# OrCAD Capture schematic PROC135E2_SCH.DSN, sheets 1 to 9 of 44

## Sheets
1 01. TABLE OF CONTENTS: title: TABLE OF CONTENTS; rev: E2
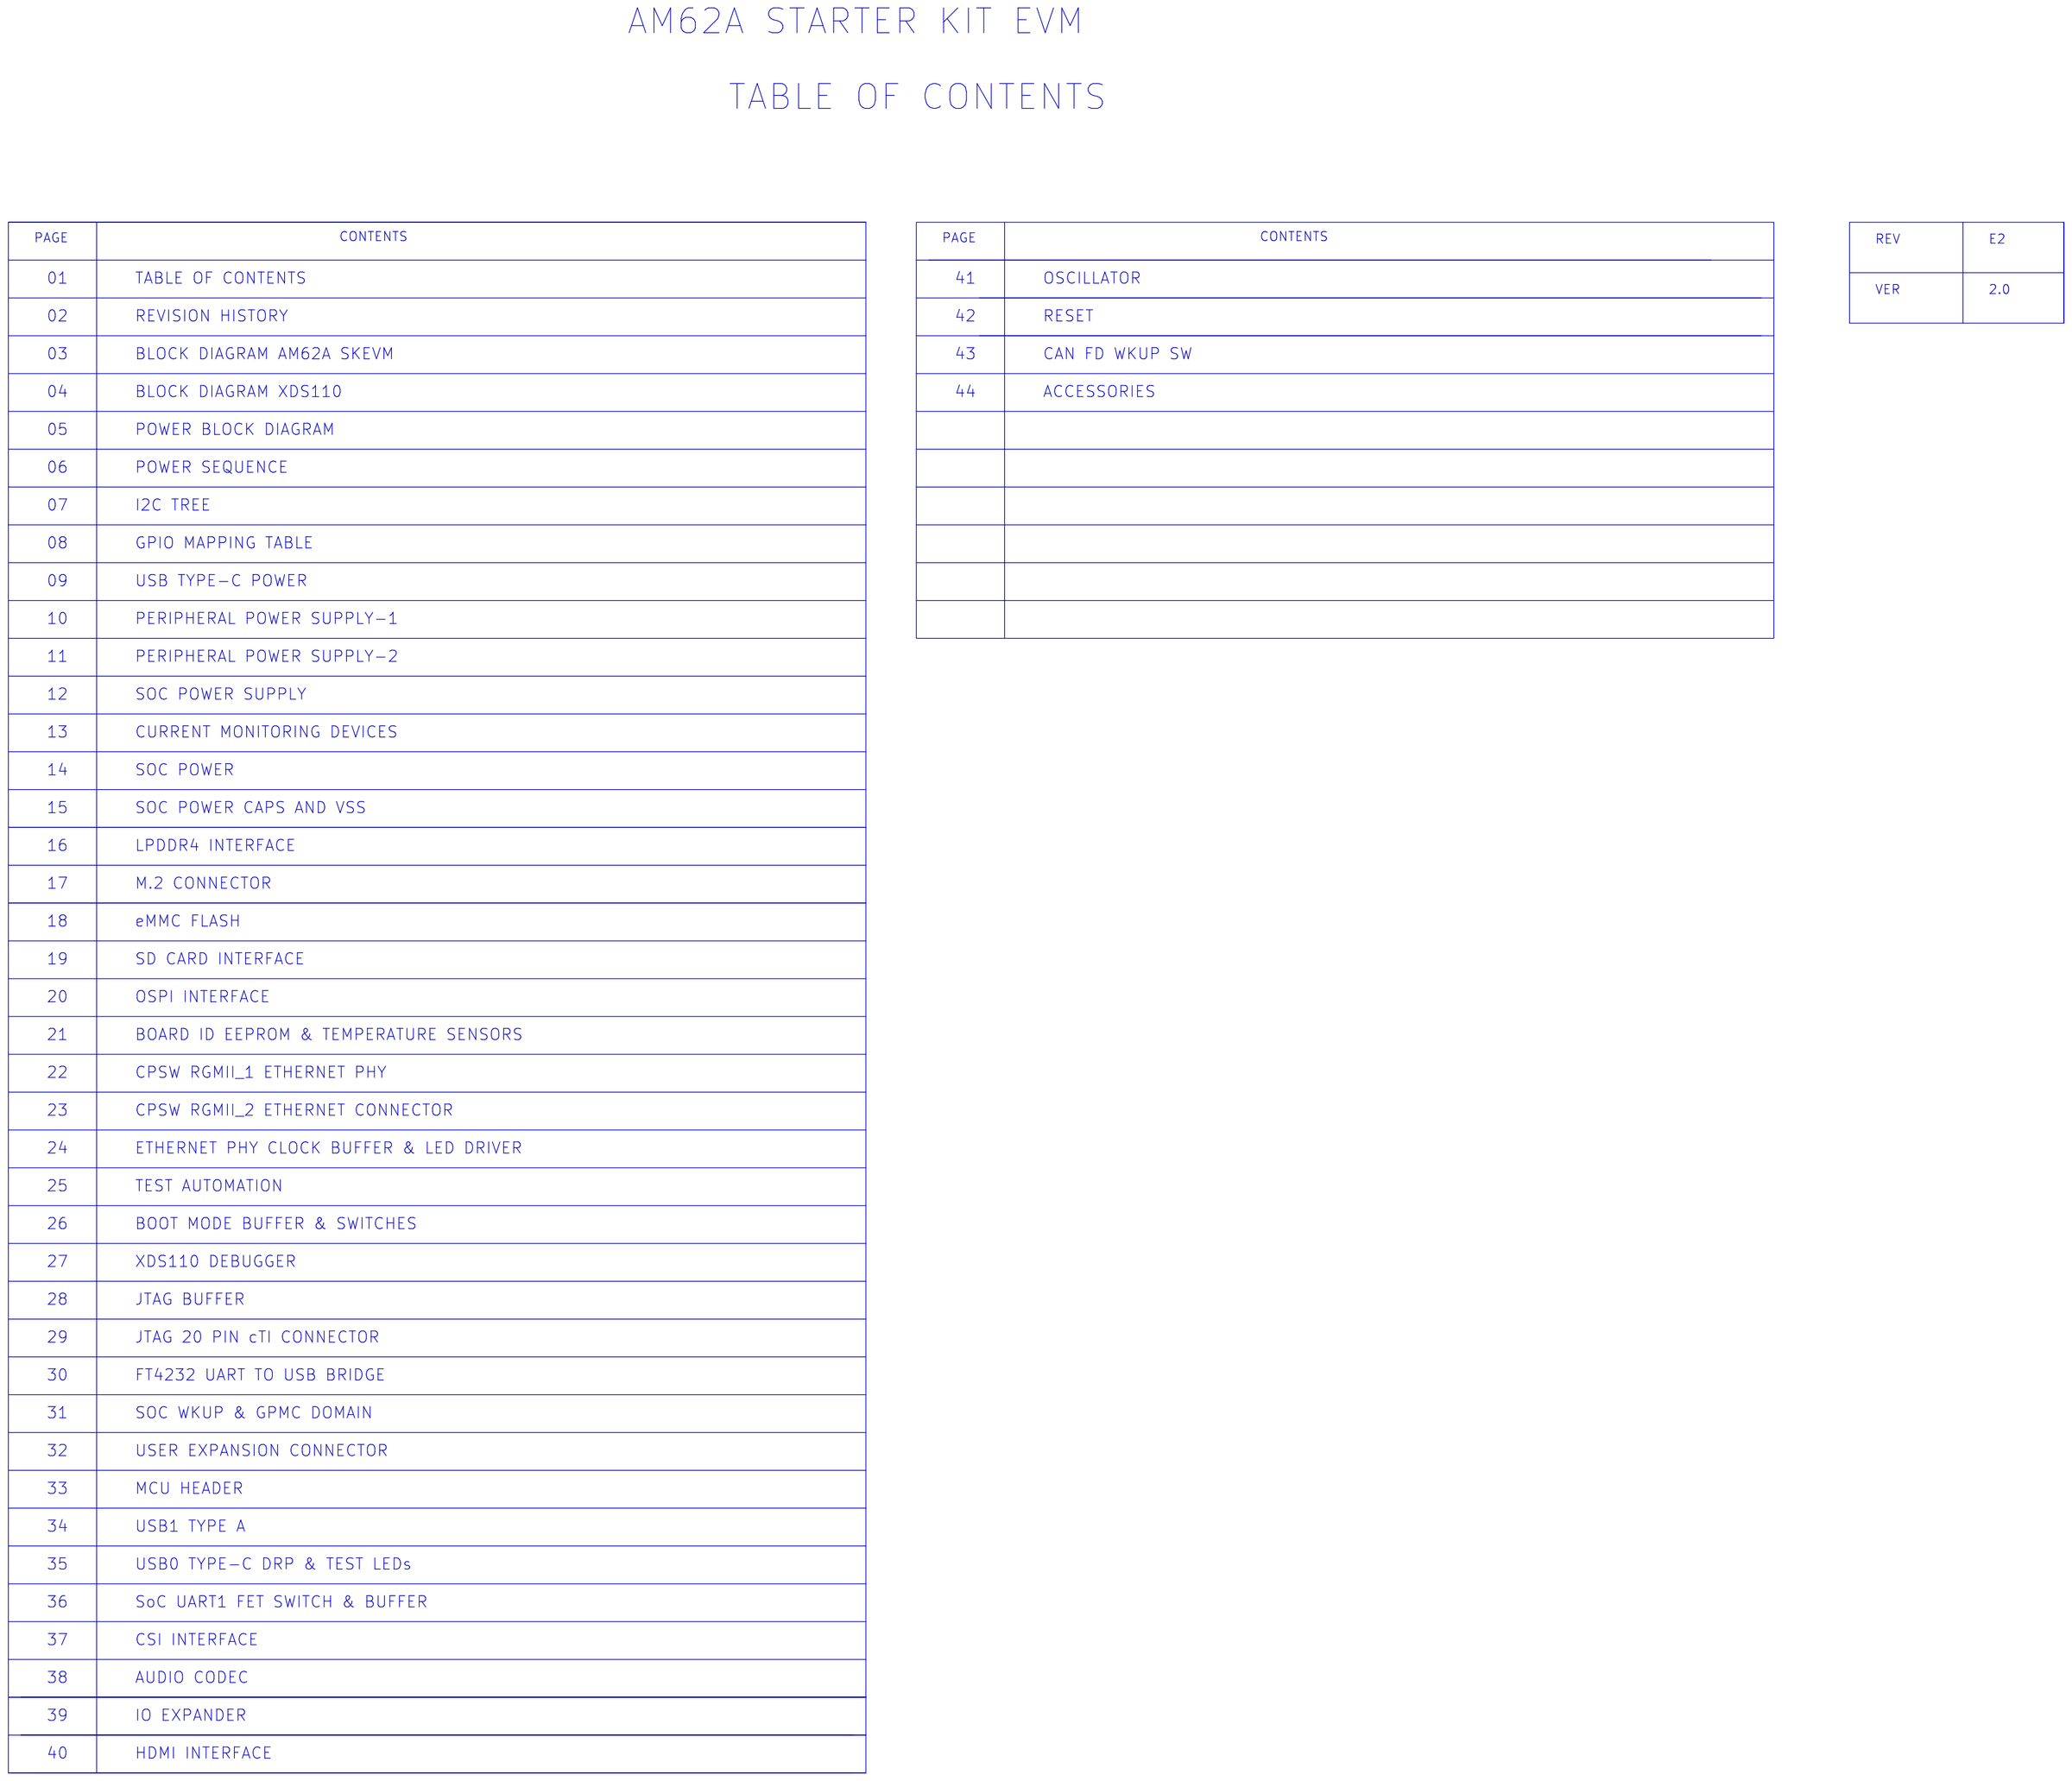
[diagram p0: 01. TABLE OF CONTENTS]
2 02. REVISION HISTORY: title: REVISION HISTORY
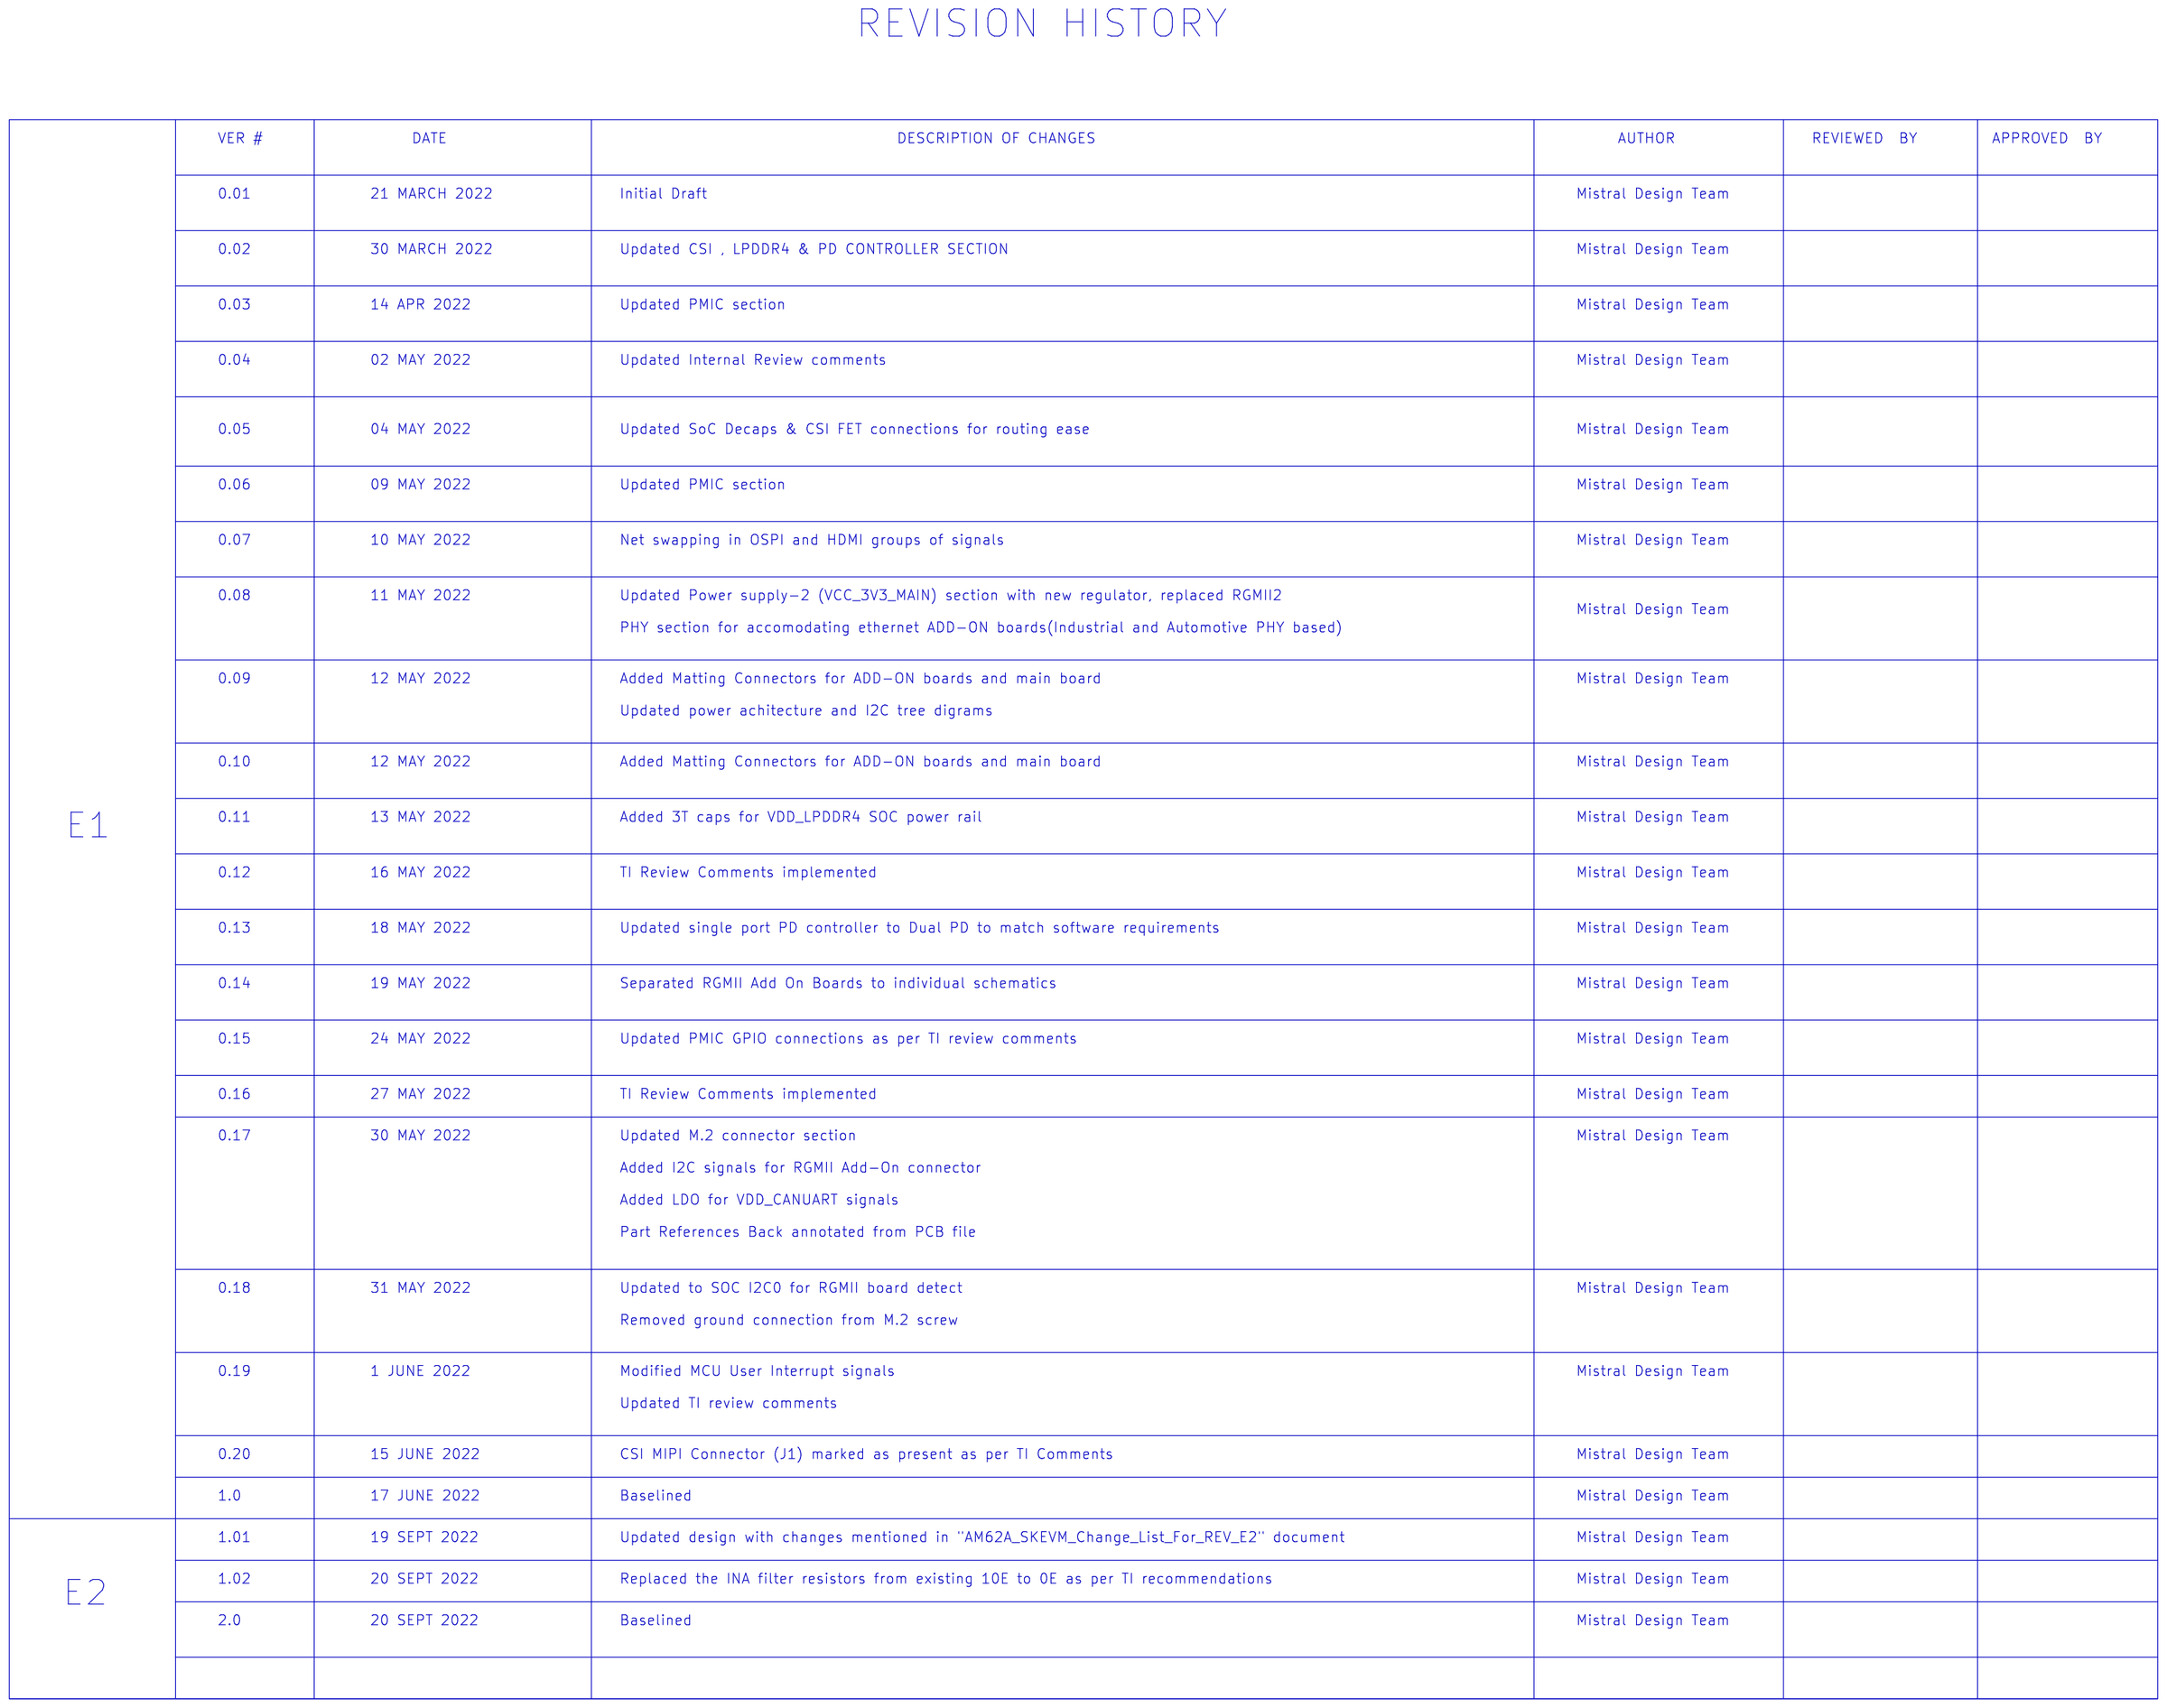
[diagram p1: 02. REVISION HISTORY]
3 03. BLOCK DGM AM62A-SKEVM: title: BLOCK DIAGRAM AM62A_ SKEVM
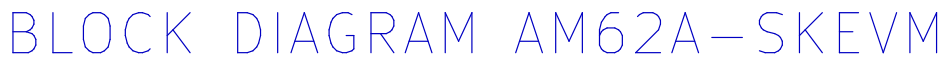
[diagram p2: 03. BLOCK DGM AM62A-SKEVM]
4 04. BLOCK DIAGRAM_XDS110: title: BLOCK DIAGRAM_XDS110
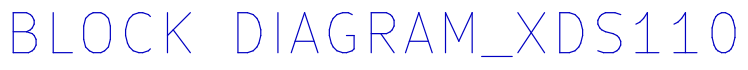
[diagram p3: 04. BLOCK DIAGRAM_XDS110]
5 05. POWER BLOCK DGM: title: POWER BLOCK DGM
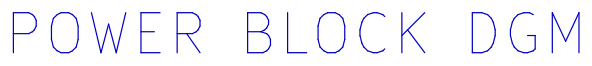
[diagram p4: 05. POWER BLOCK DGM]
6 06. POWER SEQUENCE: title: POWER SEQUENCE
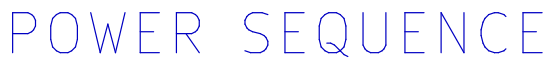
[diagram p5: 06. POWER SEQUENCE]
7 07. I2C TREE: title: I2C TREE
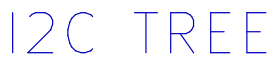
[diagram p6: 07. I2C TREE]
8 08. GPIO MAPPING TABLE: title: GPIO MAPPING TABLE
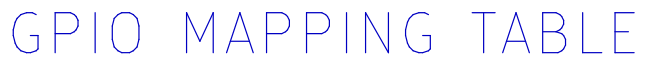
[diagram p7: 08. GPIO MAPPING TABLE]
9 09. USB TYPE-C POWER: size C; title: USB TYPE-C
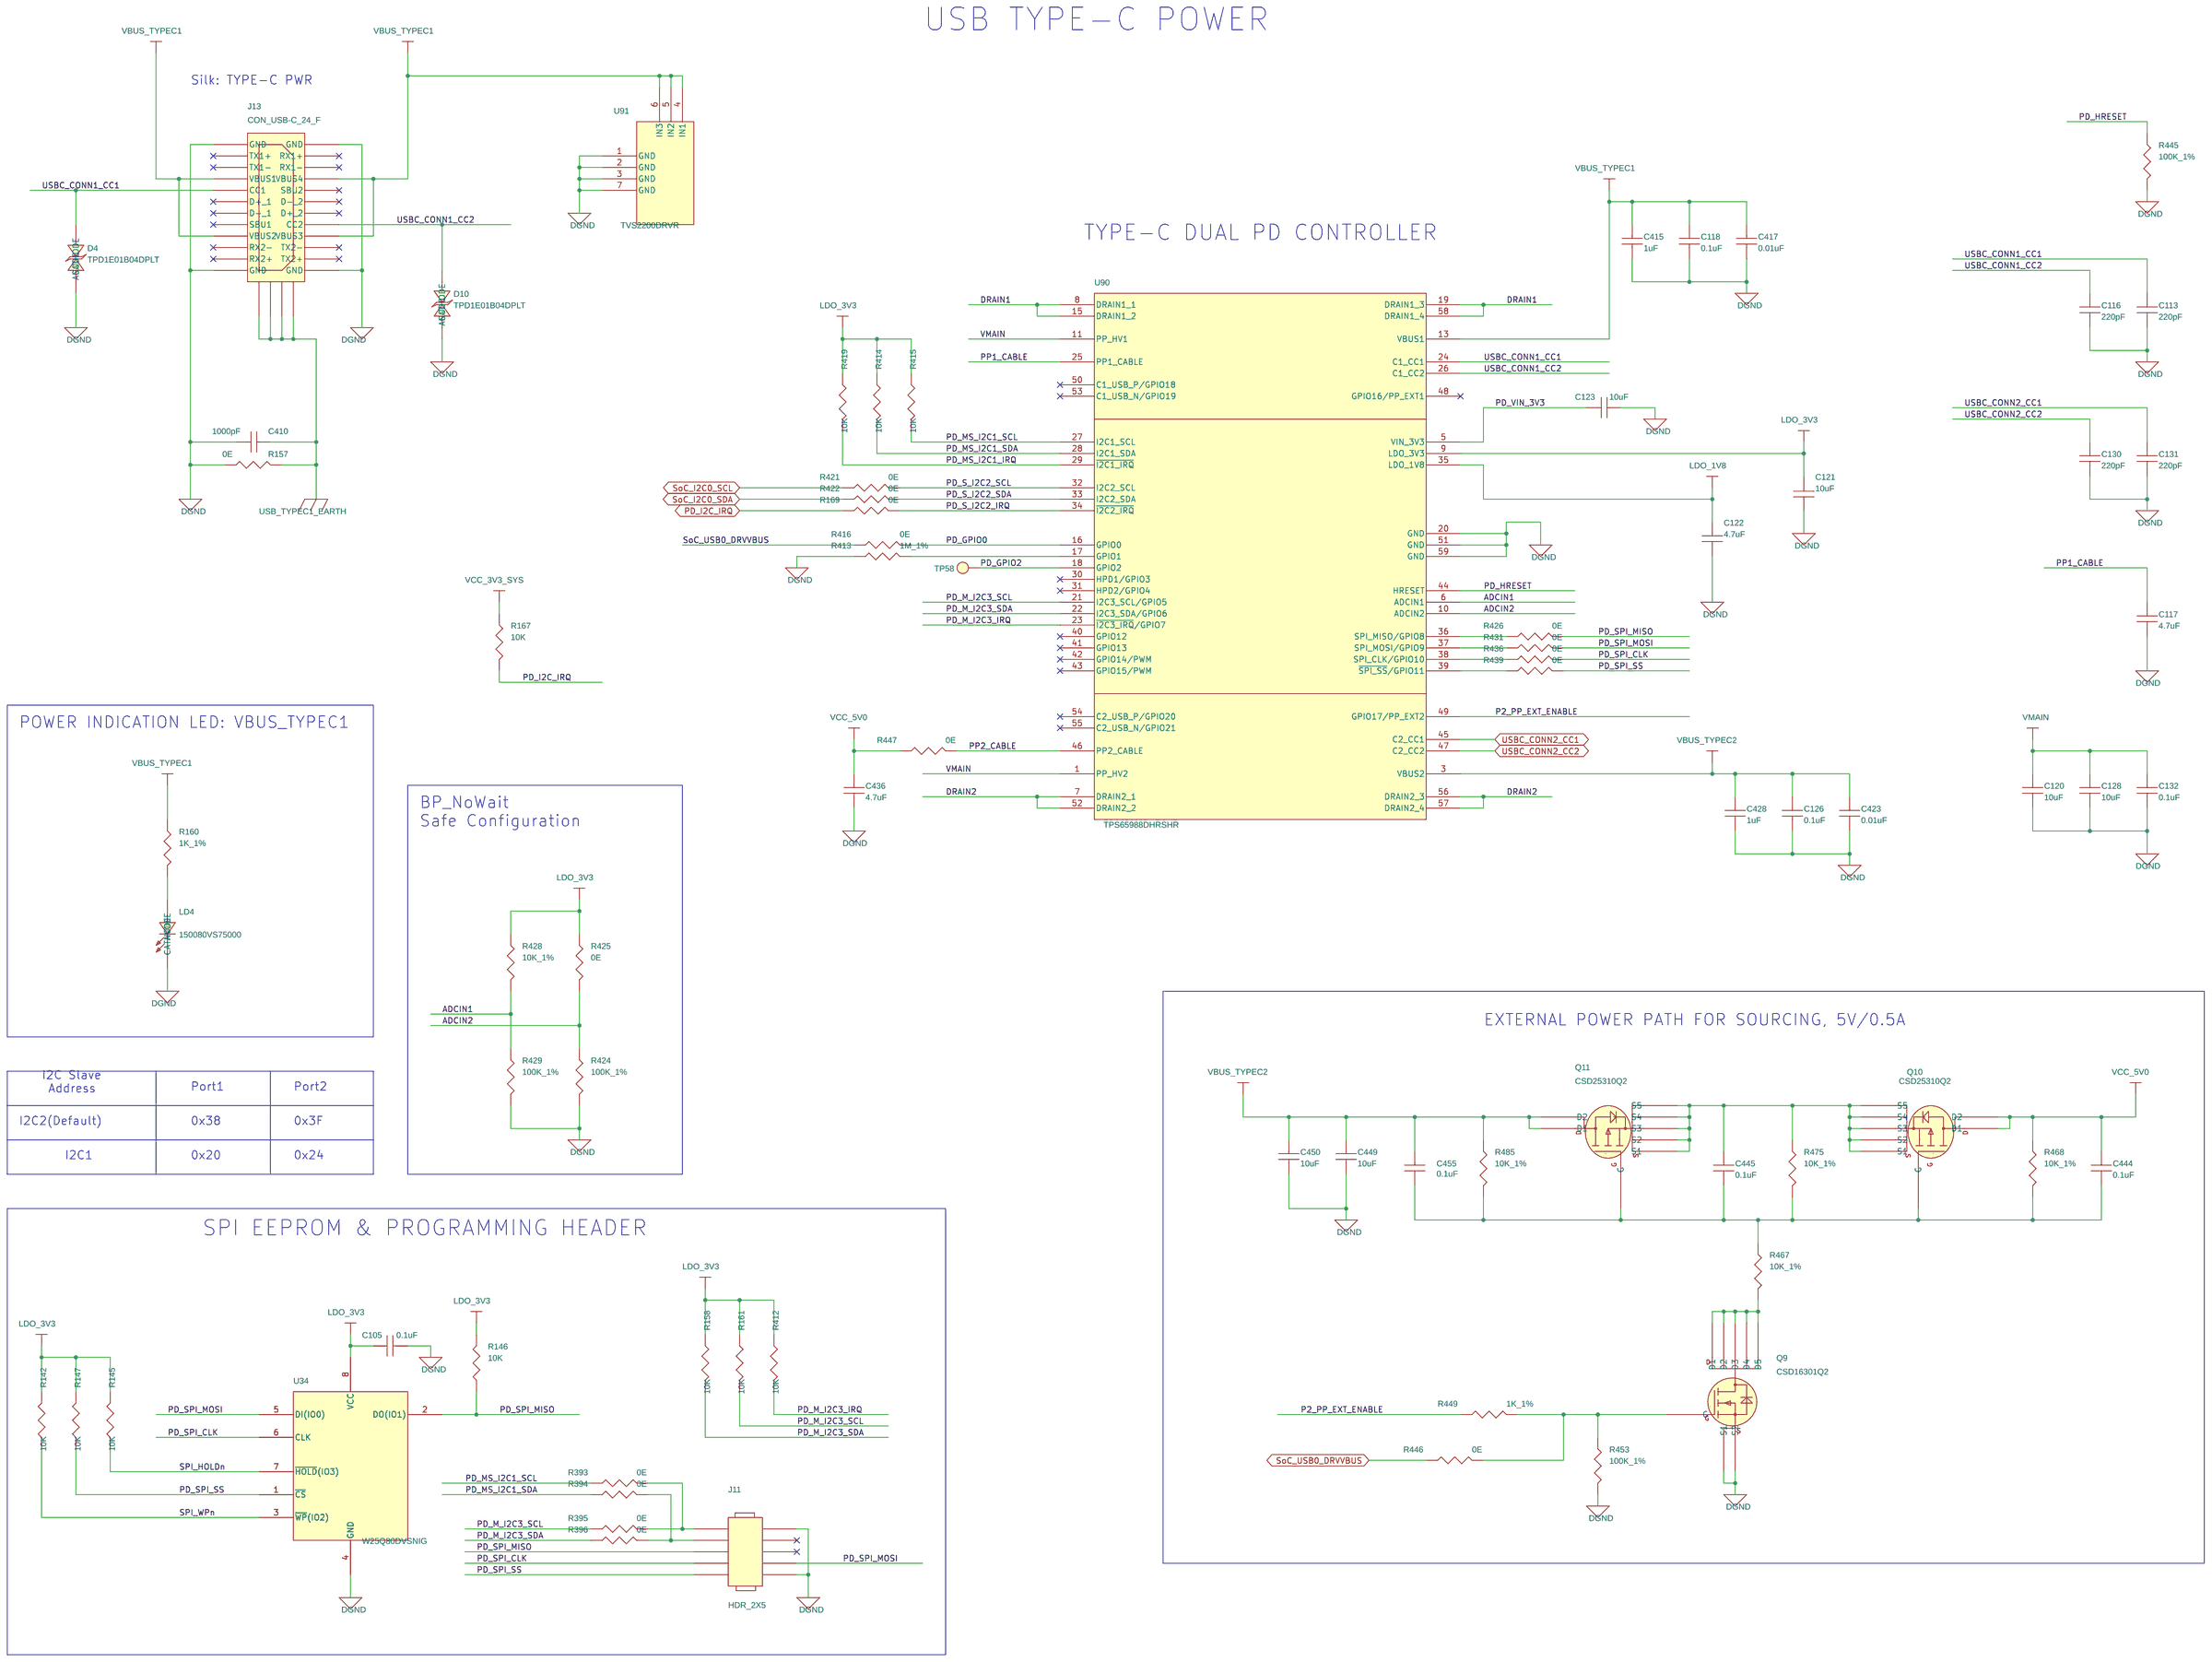
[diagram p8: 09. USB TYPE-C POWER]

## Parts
C105  0.1uF  [CAP0201_0-5]
C113  220pF  [CAP0402_0-75]
C116  220pF  [CAP0402_0-75]
C117  4.7uF  [CAP0402_0-75]
C118  0.1uF  [CAP0402_0-75]
C120  10uF  [CAP0603_1]
C121  10uF  [CAP0402_0-75]
C122  4.7uF  [CAP0402_0-75]
C123  10uF  [CAP0402_0-75]
C126  0.1uF  [CAP0402_0-75]
C128  10uF  [CAP0603_1]
C130  220pF  [CAP0402_0-75]
C131  220pF  [CAP0402_0-75]
C132  0.1uF  [CAP0402_0-75]
C410  1000pF  [CAP1206_1-75]
C415  1uF  [CAP0805_1-5]
C417  0.01uF  [CAP0201_0-5]
C423  0.01uF  [CAP0201_0-5]
C428  1uF  [CAP0805_1-5]
C436  4.7uF  [CAP0402_0-75]
C444  0.1uF  [CAP0201_0-5]
C445  0.1uF  [CAP0201_0-5]
C449  10uF  [CAP0603_1]
C450  10uF  [CAP0603_1]
C455  0.1uF  [CAP0201_0-5]
D4  TPD1E01B04DPLT  [DIO_DFN0201_0-4]
D10  TPD1E01B04DPLT  [DIO_DFN0201_0-4]
J11  HDR_2X5  [HDR_2X5_PEC05DAAN_S_T_8-6]
J13  CON_USB-C_24_F  [CON_USBC24_2012670_S_R_S_3-9]
LD4  150080VS75000  [LED_150080VS75000_80X50_SMD_0-8]
Q9  CSD16301Q2  [WSON6_CSD13202Q2_80X80_0-8]
Q10  CSD25310Q2  [SON6_CSD17313Q2_80X80]
Q11  CSD25310Q2  [SON6_CSD17313Q2_80X80]
R142  10K  [RES0201_0-5]
R145  10K  [RES0201_0-5]
R146  10K  [RES0201_0-5]
R147  10K  [RES0201_0-5]
R157  0E  [RES0603_0-75]
R158  10K  [RES0201_0-5]
R160  1K_1%  [RES0402_0-5]
R161  10K  [RES0201_0-5]
R167  10K  [RES0201_0-5]
R169  0E  [RES0201_0-5]
R393  0E  [RES0201_0-5]
R394  0E  [RES0201_0-5]
R395  0E  [RES0201_0-5]
R396  0E  [RES0201_0-5]
R412  10K  [RES0201_0-5]
R413  1M_1%  [RES0402_0-5]
R414  10K  [RES0201_0-5]
R415  10K  [RES0201_0-5]
R416  0E  [RES0201_0-5]
R419  10K  [RES0201_0-5]
R421  0E  [RES0201_0-5]
R422  0E  [RES0201_0-5]
R424  100K_1%  [RES0402_0-5]
R425  0E  [RES0201_0-5]
R426  0E  [RES0201_0-5]
R428  10K_1%  [RES0201_0-5]
R429  100K_1%  [RES0402_0-5]
R431  0E  [RES0201_0-5]
R436  0E  [RES0201_0-5]
R439  0E  [RES0201_0-5]
R445  100K_1%  [RES0201_0-5]
R446  0E  [RES0201_0-5]
R447  0E  [RES0402_0-5]
R449  1K_1%  [RES0402_0-5]
R453  100K_1%  [RES0402_0-5]
R467  10K_1%  [RES0201_0-5]
R468  10K_1%  [RES0201_0-5]
R475  10K_1%  [RES0201_0-5]
R485  10K_1%  [RES0201_0-5]
TP58  TP20_SMD  [TP20_SMD]
U34  W25Q80DVSNIG  [SOIC8_1-8]
U90  TPS65988DHRSHR  [VQFN56_TPS65987D_280X280_1]
U91  TVS2200DRVR  [SON6_25-59_85X85_0-8]

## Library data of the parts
C105 C444 C445 C455 = CAP: CAP CERAMIC 0.1uF 16V 10% X5R 0201; Chkd/date: MANIRAJA/230118; Crtd /date: MANIRAJA/230118; Custom_Duty: 15%; Customs_HS_Code: 85322990; Distributor_name: DIGIKEY; Distributor_part_number: 490-14305-1-ND; Footprint Path: Y:\MIS_DATABASE\Library\ALTIUM_TOOL\PCB_FOOTPRINTS\Altium_Footprint_Lib.PcbLib; Height: 0.33MM; Library Path: Y:\MIS_DATABASE\Library\ALTIUM_TOOL\SCHEMATICS_PARTS\MS_DISCRETE_Library.schlib; Mfr_name: MURATA; Mfr_part_number: GRM033R61C104KE14D; Mistral Part No: 120009030072-R; Package: 0201; Part_type: CAPACITORS\CERAMIC; Project: TI_MAXIE_CPB; RoHS: RoHS; Temperature: -55°C+85°C; Tolerance: 10%; Voltage: 16V; Wattage: NA; Weight: 0.33mg; Datasheet: Y:\MIS_DATABASE\DATASHEETS\CAPACITORS\GRM033R61C104KE14.PDF
C113 C116 C130 C131 = CAP: CAP CERAMIC 220pF 100V 5% C0G(NP0) 0402; Chkd/date: MANIRAJA/061021; Crtd /date: ALVY/051021; Custom_Duty: 15%; Customs_HS_Code: 85322990; Distributor_name: DIGIKEY; Distributor_part_number: 490-GRM1555C2A221JE01DTR-ND; Footprint Path: Y:\MIS_DATABASE\Library\ALTIUM_TOOL\PCB_FOOTPRINTS\Altium_Footprint_Lib.PcbLib; Height: 0.55MM; Library Path: Y:\MIS_DATABASE\Library\ALTIUM_TOOL\SCHEMATICS_PARTS\MS_DISCRETE_Library.schlib; Mfr_name: MURATA; Mfr_part_number: GRM1555C2A221JE01D; Mistral Part No: 120021100001-R; Package: 0402; Part_type: CAPACITORS\CERAMIC; Project: TI_AM62x SKEVM_BRD; RoHS: RoHS; Temperature: -55°C+125°C; Tolerance: 5%; Voltage: 100V; Wattage: NA; Weight: 1.6mg; Datasheet: Y:\MIS_DATABASE\DATASHEETS\CAPACITORS\GRM1555C2A221JE01.PDF
C117 C122 C436 = CAP: CAP CERAMIC 4.7uF 10V 20% X5R 0402; Chkd/date: MANIRAJA/110718; Crtd /date: ALVY/110718; Custom_Duty: 15%; Customs_HS_Code: 85322990; Distributor_name: DIGIKEY; Distributor_part_number: 490-14306-1-ND; Footprint Path: Y:\MIS_DATABASE\Library\ALTIUM_TOOL\PCB_FOOTPRINTS\Altium_Footprint_Lib.PcbLib; Height: 0.65MM; Library Path: Y:\MIS_DATABASE\Library\ALTIUM_TOOL\SCHEMATICS_PARTS\MS_DISCRETE_Library.schlib; Mfr_name: MURATA; Mfr_part_number: GRM155R61A475MEAAD; Mistral Part No: 120012060002-R; Package: 0402; Part_type: CAPACITORS\CERAMIC; Project: TI_J7SVB_PCIE_ADD-ON-CARD; RoHS: RoHS; Temperature: -55°C+85°C; Tolerance: 20%; Voltage: 10V; Wattage: NA; Weight: 14mg; Datasheet: Y:\MIS_DATABASE\DATASHEETS\CAPACITORS\GRM155R61A475MEAAD.PDF
C118 C126 C132 = CAP: CAP CERAMIC 0.1uF 50V 10% X7R 0402; Chkd/date: MANIRAJA/261020; Crtd /date: ALVY/211020; Custom_Duty: 15%; Customs_HS_Code: 85322990; Distributor_name: DIGIKEY; Distributor_part_number: 490-10700-1-ND; Footprint Path: Y:\MIS_DATABASE\Library\ALTIUM_TOOL\PCB_FOOTPRINTS\Altium_Footprint_Lib.PcbLib; Height: 0.55MM; Library Path: Y:\MIS_DATABASE\Library\ALTIUM_TOOL\SCHEMATICS_PARTS\MS_DISCRETE_Library.schlib; Mfr_name: MURATA; Mfr_part_number: GRM155R71H104KE14D; Mistral Part No: 120011100014-R; Package: 0402; Part_type: CAPACITORS\CERAMIC; Project: J7_CP; RoHS: RoHS; Temperature: -55°C+125°C; Tolerance: 10%; Voltage: 50V; Wattage: NA; Weight: 3.1mg; Datasheet: Y:\MIS_DATABASE\DATASHEETS\CAPACITORS\GRM155R71H104KE14.PDF
C120 C128 C449 C450 = CAP: CAP CERAMIC 10uF 35V 20% X5R 0603; Chkd/date: MANIRAJA/170519; Crtd /date: ALVY/160519; Custom_Duty: 15%; Customs_HS_Code: 85322990; Distributor_name: DIGIKEY; Distributor_part_number: 490-13248-1-ND; Footprint Path: Y:\MIS_DATABASE\Library\ALTIUM_TOOL\PCB_FOOTPRINTS\Altium_Footprint_Lib.PcbLib; Height: 1.00MM; Library Path: Y:\MIS_DATABASE\Library\ALTIUM_TOOL\SCHEMATICS_PARTS\MS_DISCRETE_Library.schlib; Mfr_name: MURATA; Mfr_part_number: GRM188R6YA106MA73D; Mistral Part No: 120019050016-R; Package: 0603; Part_type: CAPACITORS\CERAMIC; Project: BRUKER_SD820_COMMONDO; RoHS: RoHS; Temperature: -55°C+85°C; Tolerance: 20%; Voltage: 35V; Wattage: NA; Weight: 9mg; Datasheet: Y:\MIS_DATABASE\DATASHEETS\CAPACITORS\GRM188R6YA106MA73.PDF
C121 C123 = CAP: CAP CERAMIC 10uF 10V 20% X5R 0402; Chkd/date: MANIRAJA/300520; Crtd /date: ALVY/260520; Custom_Duty: 15%; Customs_HS_Code: 85322990; Distributor_name: DIGIKEY; Distributor_part_number: 490-GRM155R61A106ME11DTR-ND; Footprint Path: Y:\MIS_DATABASE\Library\ALTIUM_TOOL\PCB_FOOTPRINTS\Altium_Footprint_Lib.PcbLib; Height: 0.55MM; Library Path: Y:\MIS_DATABASE\Library\ALTIUM_TOOL\SCHEMATICS_PARTS\MS_DISCRETE_Library.schlib; Mfr_name: MURATA; Mfr_part_number: GRM155R61A106ME11D; Mistral Part No: 120013110019-R; Package: 0402; Part_type: CAPACITORS\CERAMIC; Project: QCS610_NANOSOM; RoHS: RoHS; Temperature: -55°C+85°C; Tolerance: 20%; Voltage: 10V; Wattage: NA; Weight: 3.1mg; Datasheet: Y:\MIS_DATABASE\DATASHEETS\CAPACITORS\MURATA-GXX-SER_NOV17.PDF
C410 = CAP: CAP CERAMIC 1000pF 2KV 10% X7R 1206; Chkd/date: SHREESHAIL/291106; Crtd /date: MAZHAR/281106; Custom_Duty: 15%; Customs_HS_Code: 85322990; Distributor_name: DIGIKEY; Distributor_part_number: 478-2956-1-ND; Footprint Path: Y:\MIS_DATABASE\Library\ALTIUM_TOOL\PCB_FOOTPRINTS\Altium_Footprint_Lib.PcbLib; Height: 1.52MM; Library Path: Y:\MIS_DATABASE\Library\ALTIUM_TOOL\SCHEMATICS_PARTS\MS_DISCRETE_Library.schlib; Mfr_name: AVX CORPORATION; Mfr_part_number: 1206GC102KAT1A; Mistral Part No: 120015080006-R; Package: 1206; Part_type: CAPACITORS\CERAMIC; Project: ADR1B; RoHS: RoHS; Temperature: -55°C+125°C; Tolerance: 10%; Voltage: 2KV; Wattage: NA; Weight: 16.2mg; Datasheet: Y:\MIS_DATABASE\DATASHEETS\CAPACITORS\AVX_HV-MLC.PDF
C415 C428 = CAP: CAP CERAMIC 1uF 100V 10% X7S 0805; Chkd/date: MANIRAJA/160921; Crtd /date: ALVY/150921; Custom_Duty: 15%; Customs_HS_Code: 85322990; Distributor_name: DIGIKEY; Distributor_part_number: 490-14464-1-ND; Footprint Path: Y:\MIS_DATABASE\Library\ALTIUM_TOOL\PCB_FOOTPRINTS\Altium_Footprint_Lib.PcbLib; Height: 1.45MM; Library Path: Y:\MIS_DATABASE\Library\ALTIUM_TOOL\SCHEMATICS_PARTS\MS_DISCRETE_Library.schlib; Mfr_name: MURATA; Mfr_part_number: GRM21BC72A105KE01L; Mistral Part No: 120013030002-R; Package: 0805; Part_type: CAPACITORS\CERAMIC; Project: TI_AM62x SKEVM_BRD; RoHS: RoHS; Temperature: -55°C+125°C; Tolerance: 10%; Voltage: 100V; Wattage: NA; Weight: 6.4mg; Datasheet: Y:\MIS_DATABASE\DATASHEETS\CAPACITORS\GRM21BC72A105KE01.PDF
C417 C423 = CAP: CAP CERAMIC 0.01uF 25V 10% X5R 0201; Chkd/date: MANIRAJA/230118; Crtd /date: MANIRAJA/230118; Custom_Duty: 15%; Customs_HS_Code: 85322990; Distributor_name: DIGIKEY; Distributor_part_number: GRM033R61E103KA12J-ND; Footprint Path: Y:\MIS_DATABASE\Library\ALTIUM_TOOL\PCB_FOOTPRINTS\Altium_Footprint_Lib.PcbLib; Height: 0.33MM; Library Path: Y:\MIS_DATABASE\Library\ALTIUM_TOOL\SCHEMATICS_PARTS\MS_DISCRETE_Library.schlib; Mfr_name: MURATA; Mfr_part_number: GRM033R61E103KA12J; Mistral Part No: 120018010007-R; Package: 0201; Part_type: CAPACITORS\CERAMIC; Project: TI_MAXIE_CPB; RoHS: RoHS; Temperature: -55°C+85°C; Tolerance: 10%; Voltage: 25V; Wattage: NA; Weight: 0.33mg; Datasheet: Y:\MIS_DATABASE\DATASHEETS\CAPACITORS\GRM033R61E103KA12.PDF
D4 D10 = DIODE_TVS_DUAL: DIODE 1CH ESD PROTECTION FOR USB TYPE-C AND THUNDERBOLT3 X2SON2; Chkd/date: MANIRAJA/230920; Crtd /date: ALVY/230920; Custom_Duty: 15%; Customs_HS_Code: 85412900; Distributor_name: DIGIKEY; Distributor_part_number: 296-44484-1-ND; Footprint Path: Y:\MIS_DATABASE\Library\ALTIUM_TOOL\PCB_FOOTPRINTS\Altium_Footprint_Lib.PcbLib; Height: 0.32MM; Library Path: Y:\MIS_DATABASE\Library\ALTIUM_TOOL\SCHEMATICS_PARTS\MS_DISCRETE_Library.schlib; Mfr_name: TEXAS INSTRUMENTS; Mistral Part No: 130020090037-R; Package: X2SON2; Part_type: DIODE\TVS; Project: AM64X_SKEVM; RoHS: RoHS; Temperature: -40°C+125°C; Tolerance: NA; Voltage: NA; Wattage: NA; Weight: 0.2mg; Datasheet: Y:\MIS_DATABASE\DATASHEETS\DISCRETES\DIODES\TPD1E01B04.PDF
J11 = HEADER_5X2: CON HDR 2X5 2.54MM PITCH ST TH; Chkd/date: MANIRAJA/060821; Crtd /date: ALVY/060821; Custom_Duty: 24%; Customs_HS_Code: 85369090; Distributor_name: DIGIKEY; Distributor_part_number: S2012E-05-ND; Footprint Path: Y:\MIS_DATABASE\Library\ALTIUM_TOOL\PCB_FOOTPRINTS\Altium_Footprint_Lib.PcbLib; Height: 8.58MM; Library Path: Y:\MIS_DATABASE\Library\ALTIUM_TOOL\SCHEMATICS_PARTS\MS_CONNECTOR_Library.schlib; Mfr_name: SULLINS CONNECTOR; Mfr_part_number: PEC05DAAN; Mistral Part No: 150021080010-R; Package: THRU-HOLE; Part_type: CONNECTOR\HEADERS; Project: TI_AM335x SK_BRD; RoHS: RoHS; Temperature: -65°C+125°C; Tolerance: NA; Voltage: NA; Wattage: NA; Weight: NA; Datasheet: Y:\MIS_DATABASE\DATASHEETS\CONNECTORS\XXCXXDXXN.PDF
J13 = CON_USB-C_24_1240183621: CON USB-C TYPE 24POS FEMALE RT SMD; Chkd/date: MANIRAJA/050618; Crtd /date: ALVY/040618; Custom_Duty: 24%; Customs_HS_Code: 85369090; Distributor_name: DIGIKEY; Distributor_part_number: WM17992CT-ND; Footprint Path: Y:\MIS_DATABASE\Library\ALTIUM_TOOL\PCB_FOOTPRINTS\Altium_Footprint_Lib.PcbLib; Height: 3.86MM; Library Path: Y:\MIS_DATABASE\Library\ALTIUM_TOOL\SCHEMATICS_PARTS\MS_CONNECTOR_Library.schlib; Mfr_name: MOLEX; Mfr_part_number: 2012670005; Mistral Part No: 150018060002-R; Package: SMD; Part_type: CONNECTOR\USB; Project: TI_J7SVB_USB_ADD-ON-CARD; RoHS: RoHS; Temperature: -40°C+105°C; Tolerance: NA; Voltage: NA; Wattage: NA; Weight: 0.686g; Datasheet: Y:\MIS_DATABASE\DATASHEETS\CONNECTORS\2012670X.PDF
LD4 = DIODE_LED: DIODE LED BRIGHT GREEN SMD; Chkd/date: MANIRAJA/180820; Crtd /date: ALVY/180820; Custom_Duty: 24%; Customs_HS_Code: 85439000; Distributor_name: DIGIKEY; Distributor_part_number: 732-4986-1-ND; Footprint Path: Y:\MIS_DATABASE\Library\ALTIUM_TOOL\PCB_FOOTPRINTS\Altium_Footprint_Lib.PcbLib; Height: 0.80MM; Library Path: Y:\MIS_DATABASE\Library\ALTIUM_TOOL\SCHEMATICS_PARTS\MS_OPTO_Library.schlib; Mfr_name: WURTH ELECTRONICS; Mistral Part No: 130020080012-R; Package: SMD; Part_type: OPTO\LED; Project: AM64x_EVM_BRD; RoHS: RoHS; Temperature: -40°C+85°C; Tolerance: NA; Voltage: NA; Wattage: NA; Weight: 10mg; Datasheet: Y:\MIS_DATABASE\DATASHEETS\DISCRETES\LEDS\150080VS75000.PDF
Q9 = MOSFET_CSD17313Q2: IC MOSFET N-CHANNEL NEXFET 25V WSON6; Chkd/date: ALVY/071220; Crtd /date: MANIRAJA/071220; Custom_Duty: 15%; Customs_HS_Code: 85423100; Distributor_name: DIGIKEY; Distributor_part_number: 296-25260-1-ND; Footprint Path: Y:\MIS_DATABASE\Library\ALTIUM_TOOL\PCB_FOOTPRINTS\Altium_Footprint_Lib.PcbLib; Height: 0.80MM; Library Path: Y:\MIS_DATABASE\Library\ALTIUM_TOOL\SCHEMATICS_PARTS\MS_MOSFET_Library.schlib; Mfr_name: TEXAS INSTRUMENTS; Mistral Part No: 142020120008-R; Package: WSON6; Part_type: ICS\POWER\MOSFET; Project: TI_AM243x LP EVM; RoHS: RoHS; Temperature: -55°C+150°C; Tolerance: NA; Voltage: NA; Wattage: NA; Weight: 8.7mg; Datasheet: Y:\MIS_DATABASE\DATASHEETS\ICS\POWER\CSD16301Q2.PDF
Q10 Q11 = MOSFET_CSD25310Q2: IC MOSFET P-CHANNEL WSON6; Chkd/date: VASANTHA/191215; Crtd /date: VASANTHA/191215; Custom_Duty: 15%; Customs_HS_Code: 85423100; Distributor_name: DIGIKEY; Distributor_part_number: 296-38915-1-ND; Height: 0.85MM; Mfr_name: TEXAS INSTRUMENTS; Mistral Part No: 142015120011-R; Package: WSON6; Part_type: ICS\POWER\MOSFET; Project: DUET BOARD; RoHS: RoHS; Temperature: -55°C+150°C; Tolerance: NA; Voltage: NA; Wattage: NA; Weight: NA; Datasheet: Y:\MIS_DATABASE\DATASHEETS\DISCRETES\TRANSISTORS_FETS\CSD25310Q2.PDF
R142 R145-R147 R158 R161 R167 R412 R414 R415 R419 = RESISTOR: RES 10K 1/20W 5% 0201; Chkd/date: MANIRAJA/050517; Crtd /date: MANIRAJA/050517; Custom_Duty: 15%; Customs_HS_Code: 85332119; Distributor_name: DIGIKEY; Distributor_part_number: 311-10KNCT-ND; Footprint Path: Y:\MIS_DATABASE\Library\ALTIUM_TOOL\PCB_FOOTPRINTS\Altium_Footprint_Lib.PcbLib; Height: 0.26MM; Library Path: Y:\MIS_DATABASE\Library\ALTIUM_TOOL\SCHEMATICS_PARTS\MS_DISCRETE_Library.schlib; Mfr_name: YAGEO AMERICA; Mfr_part_number: RC0201JR-0710KL; Mistral Part No: 110010070051-R; Package: 0201; Part_type: RESISTORS\FIXED; Project: GOLDEN-I LITE; RoHS: RoHS; Temperature: -55°C+125°C; Tolerance: 5%; Voltage: NA; Wattage: 1/20W; Weight: 0.17mg; Datasheet: Y:\MIS_DATABASE\DATASHEETS\RESISTORS\RCXXXXL-SER_MAR18.PDF
R157 = RESISTOR: RES 0E 1/10W 5% 0603; Chkd/date: MANIRAJA/051217; Crtd /date: BAVISH/180211; Custom_Duty: 15%; Customs_HS_Code: 85332119; Distributor_name: DIGIKEY; Distributor_part_number: 311-0.0GRCT-ND; Footprint Path: Y:\MIS_DATABASE\Library\ALTIUM_TOOL\PCB_FOOTPRINTS\Altium_Footprint_Lib.PcbLib; Height: 0.55MM; Library Path: Y:\MIS_DATABASE\Library\ALTIUM_TOOL\SCHEMATICS_PARTS\MS_DISCRETE_Library.schlib; Manufacturer: YAGEO AMERICA; Mfr_name: PANASONIC-ECG; Mfr_part_number: RC0603JR-070RL; Mistral Part No: 110011020013-R; Package: 0603; Part_type: RESISTORS\FIXED; Project: KENNEL; RoHS: RoHS; Temperature: -55°C+155°C; Tolerance: 5%; Voltage: NA; Wattage: 1/10W; Weight: 2mg; Datasheet: Y:\MIS_DATABASE\DATASHEETS\RESISTORS\RCXXXXL-SER_MAR18.PDF
R160 R449 = RESISTOR: RES 1K 1/10W 1% 0402; Chkd/date: VASANTHA/281216; Crtd /date: MAZHAR/150506; Custom_Duty: 15%; Customs_HS_Code: 85332119; Distributor_name: DIGIKEY; Distributor_part_number: P1.00KLCT-ND; Footprint Path: Y:\MIS_DATABASE\Library\ALTIUM_TOOL\PCB_FOOTPRINTS\Altium_Footprint_Lib.PcbLib; Height: 0.40MM; Library Path: Y:\MIS_DATABASE\Library\ALTIUM_TOOL\SCHEMATICS_PARTS\MS_DISCRETE_Library.schlib; Mfr_name: PANASONIC-ECG; Mfr_part_number: ERJ-2RKF1001X; Mistral Part No: 110009030411-R; Package: 0402; Part_type: RESISTORS\FIXED; Project: VOCERA; RoHS: RoHS; Temperature: -55°C+155°C; Tolerance: 1%; Voltage: NA; Wattage: 1/10W; Weight: 0.8mg; Datasheet: Y:\MIS_DATABASE\DATASHEETS\RESISTORS\PAN-ERJSER_NOV17.PDF
R169 R393-R396 R416 R421 R422 R426 R431 R436 R439 R446 = RESISTOR: RES 0E 1/20W 5% 0201; Chkd/date: NAVEED/301214; Crtd /date: MUDDU/120710; Custom_Duty: 15%; Customs_HS_Code: 85332119; Distributor_name: DIGIKEY; Distributor_part_number: 311-0.0NCT-ND; Footprint Path: Y:\MIS_DATABASE\Library\ALTIUM_TOOL\PCB_FOOTPRINTS\Altium_Footprint_Lib.PcbLib; Height: 0.26MM; Library Path: Y:\MIS_DATABASE\Library\ALTIUM_TOOL\SCHEMATICS_PARTS\MS_DISCRETE_Library.schlib; Mfr_name: YAGEO AMERICA; Mfr_part_number: RC0201JR-070RL; Mistral Part No: 110010070067-R; Package: 0201; Part_type: RESISTORS\FIXED; Project: PB_BUGBASE; RoHS: RoHS; Temperature: -55°C+125°C; Tolerance: 5%; Voltage: NA; Wattage: 1/20W; Weight: 0.17mg; Datasheet: Y:\MIS_DATABASE\DATASHEETS\RESISTORS\RCXXXXL-SER_MAR18.PDF
R413 = RESISTOR: RES 1M 1/16W 1% 0402; Chkd/date: MANIRAJA/190319; Crtd /date: MANIRAJA/190319; Custom_Duty: 15%; Customs_HS_Code: 85332119; Distributor_name: DIGIKEY; Distributor_part_number: 311-1.00MLRCT-ND; Footprint Path: Y:\MIS_DATABASE\Library\ALTIUM_TOOL\PCB_FOOTPRINTS\Altium_Footprint_Lib.PcbLib; Height: 0.40MM; Library Path: Y:\MIS_DATABASE\Library\ALTIUM_TOOL\SCHEMATICS_PARTS\MS_DISCRETE_Library.schlib; Mfr_name: YAGEO AMERICA; Mfr_part_number: RC0402FR-071ML; Mistral Part No: 110014060045-R; Package: 0402; Part_type: RESISTORS\FIXED; Project: G4SLIM; RoHS: RoHS; Temperature: -55°C+155°C; Tolerance: 1%; Voltage: NA; Wattage: 1/16W; Weight: 0.65mg; Datasheet: Y:\MIS_DATABASE\DATASHEETS\RESISTORS\RCXXXXL-SER_MAR18.PDF
R424 R429 R453 = RESISTOR: RES 100K 1/10W 1% 0402; Chkd/date: VASANTHA/201216; Crtd /date: MAZHAR/130306; Custom_Duty: 15%; Customs_HS_Code: 85332119; Distributor_name: DIGIKEY; Distributor_part_number: P100KLCT-ND; Footprint Path: Y:\MIS_DATABASE\Library\ALTIUM_TOOL\PCB_FOOTPRINTS\Altium_Footprint_Lib.PcbLib; Height: 0.40MM; Library Path: Y:\MIS_DATABASE\Library\ALTIUM_TOOL\SCHEMATICS_PARTS\MS_DISCRETE_Library.schlib; Mfr_name: PANASONIC-ECG; Mfr_part_number: ERJ-2RKF1003X; Mistral Part No: 110009030187-R; Package: 0402; Part_type: RESISTORS\FIXED; Project: J32; RoHS: RoHS; Temperature: -55°C+155°C; Tolerance: 1%; Voltage: NA; Wattage: 1/10W; Weight: 0.8mg; Datasheet: Y:\MIS_DATABASE\DATASHEETS\RESISTORS\PAN-ERJSER_NOV17.PDF
R425 = RESISTOR: RES 0E 1/20W JUMPER 0201; Chkd/date: VASANTHA/061216; Crtd /date: MAZHAR/040505; Custom_Duty: 15%; Customs_HS_Code: 85332119; Distributor_name: DIGIKEY; Distributor_part_number: P0.0AGCT-ND; Footprint Path: Y:\MIS_DATABASE\Library\ALTIUM_TOOL\PCB_FOOTPRINTS\Altium_Footprint_Lib.PcbLib; Height: 0.26MM; Library Path: Y:\MIS_DATABASE\Library\ALTIUM_TOOL\SCHEMATICS_PARTS\MS_DISCRETE_Library.schlib; Mfr_name: PANASONIC-ECG; Mfr_part_number: ERJ-1GE0R00C; Mistral Part No: 110009030078-R; Package: 0201; Part_type: RESISTORS\FIXED; Project: HS100RD; RoHS: RoHS; Temperature: -55°C+125°C; Tolerance: NA; Voltage: NA; Wattage: 1/20W; Weight: 0.15mg; Datasheet: Y:\MIS_DATABASE\DATASHEETS\RESISTORS\PAN-ERJXGE-FEB06.PDF
R428 R467 R475 = RESISTOR: RES 10K 1/20W 1% 0201; Chkd/date: VASANTHA/270117; Crtd /date: MANIRAJA/270117; Custom_Duty: 15%; Customs_HS_Code: 85332119; Distributor_name: DIGIKEY; Distributor_part_number: 311-10.0KMCT-ND; Footprint Path: Y:\MIS_DATABASE\Library\ALTIUM_TOOL\PCB_FOOTPRINTS\Altium_Footprint_Lib.PcbLib; Height: 0.26MM; Library Path: Y:\MIS_DATABASE\Library\ALTIUM_TOOL\SCHEMATICS_PARTS\MS_DISCRETE_Library.schlib; Mfr_name: YAGEO AMERICA; Mfr_part_number: RC0201FR-0710KL; Mistral Part No: 110011040018-R; Package: 0201; Part_type: RESISTORS\FIXED; Project: GOLDEN-I LITE; RoHS: RoHS; Temperature: -55°C+125°C; Tolerance: 1%; Voltage: NA; Wattage: 1/20W; Weight: 0.17mg; Datasheet: Y:\MIS_DATABASE\DATASHEETS\RESISTORS\RCXXXXL-SER_MAR18.PDF
R445 = RESISTOR: RES 100K 1/20W 1% 0201; Chkd/date: MANIRAJA/120520; Crtd /date: ALVY/120520; Custom_Duty: 15%; Customs_HS_Code: 85332119; Distributor_name: DIGIKEY; Distributor_part_number: 311-100KMCT-ND; Footprint Path: Y:\MIS_DATABASE\Library\ALTIUM_TOOL\PCB_FOOTPRINTS\Altium_Footprint_Lib.PcbLib; Height: 0.26MM; Library Path: Y:\MIS_DATABASE\Library\ALTIUM_TOOL\SCHEMATICS_PARTS\MS_DISCRETE_Library.schlib; Mfr_name: YAGEO AMERICA; Mfr_part_number: RC0201FR-07100KL; Mistral Part No: 110009060005-R; Package: 0201; Part_type: RESISTORS\FIXED; Project: SD865_NANOSOM; RoHS: RoHS; Temperature: -55°C+125°C; Tolerance: 1%; Voltage: NA; Wattage: 1/20W; Weight: 9mg; Datasheet: Y:\MIS_DATABASE\DATASHEETS\RESISTORS\RCXXXXL-SER_MAR18.PDF
R447 = RESISTOR: RES 0E 1/16W JUMPER 0402; Chkd/date: VASANTHA/201216; Crtd /date: MUDDU/190810; Custom_Duty: 15%; Customs_HS_Code: 85332119; Distributor_name: DIGIKEY; Distributor_part_number: 541-0.0JCT-ND; Footprint Path: Y:\MIS_DATABASE\Library\ALTIUM_TOOL\PCB_FOOTPRINTS\Altium_Footprint_Lib.PcbLib; Height: 0.40MM; Library Path: Y:\MIS_DATABASE\Library\ALTIUM_TOOL\SCHEMATICS_PARTS\MS_DISCRETE_Library.schlib; Mfr_name: VISHAY; Mfr_part_number: CRCW04020000Z0ED; Mistral Part No: 110010080019-R; Package: 0402; Part_type: RESISTORS\FIXED; Project: PB_BUGBASE; RoHS: RoHS; Temperature: -55°C+155°C; Tolerance: NA; Voltage: NA; Wattage: 1/16W; Weight: 0.65mg; Datasheet: Y:\MIS_DATABASE\DATASHEETS\RESISTORS\CRCW0603.PDF
R468 R485 = RESISTOR: RES 10K 1/20W 1% 0201; Chkd/date: MANIRAJA/260618; Crtd /date: ALVY/260618; Custom_Duty: 15%; Customs_HS_Code: 85332119; Distributor_name: DIGIKEY; Distributor_part_number: 541-10.0KABCT-ND; Footprint Path: Y:\MIS_DATABASE\Library\ALTIUM_TOOL\PCB_FOOTPRINTS\Altium_Footprint_Lib.PcbLib; Height: 0.28MM; Library Path: Y:\MIS_DATABASE\Library\ALTIUM_TOOL\SCHEMATICS_PARTS\MS_DISCRETE_Library.schlib; Mfr_name: VISHAY; Mfr_part_number: CRCW020110K0FNED; Mistral Part No: 110018060032-R; Package: 0201; Part_type: RESISTORS\FIXED; Project: NEXTNAV_LPRX_BOARD; RoHS: RoHS; Temperature: -55°C+155°C; Tolerance: 1%; Voltage: NA; Wattage: 1/20W; Weight: 0.17mg; Datasheet: Y:\MIS_DATABASE\DATASHEETS\RESISTORS\CRCW0201.PDF
TP58 = TESTPOINT: TESTPOINT CIR 20 SMD; Chkd/date: SHREESHAIL/171006; Crtd /date: MAZHAR/171006; Custom_Duty: NA; Customs_HS_Code: NA; Distributor_name: NA; Distributor_part_number: NA; Footprint Path: Y:\MIS_DATABASE\Library\ALTIUM_TOOL\PCB_FOOTPRINTS\Altium_Footprint_Lib.PcbLib; Height: NA; Library Path: Y:\MIS_DATABASE\Library\ALTIUM_TOOL\SCHEMATICS_PARTS\MS_DISCRETE_Library.schlib; MECHANICAL 3D STEP FILE: NA; Mfr_name: LOCAL; Mistral Part No: NA; Package: SMD; Project: BT MODULE_CSRBC04; RoHS: NA; Temperature: NA; Tolerance: NA; Voltage: NA; Wattage: NA; Weight: NA; Datasheet: NA
U34 = W25Q80BWSNIG_SOIC8: IC SERIAL FLASH MEMORY SOIC8; Chkd/date: VASANTHA/150217; Crtd /date: MANIRAJA/150217; Custom_Duty: 15%; Customs_HS_Code: 85423100; Distributor_name: DIGIKEY; Distributor_part_number: W25Q80DVSNIG CT-ND; Height: 1.75MM; Mfr_name: WINBOND; Mfr_part_number: W25Q80DVSNIG-TR; Mistral Part No: 141117020010-R; Package: SOIC8; Part_type: ICS\DIGITAL\MEMORY; Project: SD820_NANO_SOM; RoHS: RoHS; Temperature: -40°C+85°C; Tolerance: NA; Voltage: NA; Wattage: NA; Weight: NA; Datasheet: Y:\MIS_DATABASE\DATASHEETS\ICS\MEMORY\W25Q80DVSS.PDF
U90 = TPS65988DJ_VQFN56: IC 2-PORT USB TYPE-C AND USB PD CONTROLLER WITH INTEGRATED POWER SWITCH VQFN56; Chkd/date: MANIRAJA/290721; Crtd /date: ALVY/280721; Custom_Duty: 15%; Customs_HS_Code: 85423100; Distributor_name: DIGIKEY; Distributor_part_number: 296-52068-1-ND; Footprint Path: Y:\MIS_DATABASE\Library\ALTIUM_TOOL\PCB_FOOTPRINTS\Altium_Footprint_Lib.PcbLib; Height: 1.00MM; Library Path: Y:\MIS_DATABASE\Library\ALTIUM_TOOL\SCHEMATICS_PARTS\MS_MISCPOWER_Library.schlib; Mfr_name: TEXAS INSTRUMENTS; Mistral Part No: 142021070017-R; Package: VQFN56; Part_type: ICS\POWER\MANAGEMENT; Project: TI_AM62x_SKEVM; RoHS: RoHS; Temperature: -10°C+75°C; Tolerance: NA; Voltage: NA; Wattage: NA; Weight: 127.6mg; Datasheet: Y:\MIS_DATABASE\DATASHEETS\ICS\POWER\TPS65988DHRSHR.PDF
U91 = TVS2200_WSON6: IC 22V FLAT-CLAMP SURGE PROTECTION DEVICE WSON6; Chkd/date: MANIRAJA/011021; Crtd /date: ALVY/011021; Custom_Duty: 15%; Customs_HS_Code: 85423100; Distributor_name: DIGIKEY; Distributor_part_number: 296-52187-1-ND; Footprint Path: Y:\MIS_DATABASE\Library\ALTIUM_TOOL\PCB_FOOTPRINTS\Altium_Footprint_Lib.PcbLib; Height: 0.80MM; Library Path: Y:\MIS_DATABASE\Library\ALTIUM_TOOL\SCHEMATICS_PARTS\MS_MISCPOWER_Library.schlib; Mfr_name: TEXAS INSTRUMENTS; Mistral Part No: 142021100001-R; Package: WSON6; Part_type: ICS\POWER; Project: TI_AM62x SKEVM_BRD; RoHS: RoHS; Temperature: -40°C+125°C; Tolerance: NA; Voltage: NA; Wattage: NA; Weight: 12mg; Datasheet: Y:\MIS_DATABASE\DATASHEETS\ICS\POWER\TVS2200.PDF

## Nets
DGND: C105.2 C113.2 C116.2 C117.2 C118.2 C120.2 C121.1 C122.2 C123.1 C126.2 C128.2 C130.2 C131.2 C132.2 C410.2 C415.2 C417.2 C423.2 C428.2 C436.2 C449.2 C450.2 D4.2(ANODE) D10.2(ANODE) J11.2 J11.10 J13.A1(GND) J13.A12(GND) J13.B1(GND) J13.B12(GND) LD4.1(CATHODE) Q9.4(S1) Q9.7(S2) R157.2 R413.1 R424.2 R429.2 R445.2 R453.2 U34.4(GND) U90.20(GND) U90.51(GND) U90.59(GND) U91.1(GND) U91.2(GND) U91.3(GND) U91.7(GND) ; also on sheet 10 11 12 13 14 15 16 17 18 19 20 21 22 23 24 25 26 27 28 29 30 31 32 33 34 35 36 37 38 39 40 41 42 43
VBUS_TYPEC1: C118.1 C415.1 C417.1 J13.A4(VBUS1) J13.A9(VBUS2) J13.B4(VBUS3) J13.B9(VBUS4) R160.1 U90.13(VBUS1) U91.4(IN1) U91.5(IN2) U91.6(IN3)
VBUS_TYPEC2: C126.1 C423.1 C428.1 C449.1 C450.1 C455.1 Q11.4(D1) Q11.7(D2) R485.1 U90.3(VBUS2) ; also on sheet 34 35
VCC_3V3_SYS: R167.1 ; also on sheet 10 12 13 17 18 19 21 22 23 25 26 28 29 30 32 33 34 35 36 37 38 39 40 41 42
VCC_5V0: C436.1 C444.1 Q10.4(D1) Q10.7(D2) R447.1 R468.1 ; also on sheet 10 23 32 34 37 40
ADCIN1: R428.2 R429.1 U90.6(ADCIN1)
ADCIN2: R424.1 R425.2 U90.10(ADCIN2)
DRAIN1: U90.8(DRAIN1_1) U90.15(DRAIN1_2) U90.19(DRAIN1_3) U90.58(DRAIN1_4)
DRAIN2: U90.7(DRAIN2_1) U90.52(DRAIN2_2) U90.56(DRAIN2_3) U90.57(DRAIN2_4)
LDO_1V8: C122.1 U90.35(LDO_1V8)
LDO_3V3: C105.1 C121.2 R142.1 R145.1 R146.1 R147.1 R158.1 R161.1 R412.1 R414.1 R415.1 R419.1 R425.1 R428.1 U34.8(VCC) U90.9(LDO_3V3) ; also on sheet 12
P2_PP_EXT_ENABLE: R449.1 U90.49(GPIO17/PP_EXT2)
PD_GPIO0: R416.2 U90.16(GPIO0)
PD_GPIO2: TP58.1(TP) U90.18(GPIO2)
PD_HRESET: R445.1 U90.44(HRESET)
PD_I2C_IRQ: R167.2 R169.1 ; also on sheet 39
PD_M_I2C3_IRQ: R412.2 U90.23(~{I2C3_IRQ}/GPIO7)
PD_M_I2C3_SCL: R161.2 R395.1 U90.21(I2C3_SCL/GPIO5)
PD_M_I2C3_SDA: R158.2 R396.1 U90.22(I2C3_SDA/GPIO6)
PD_MS_I2C1_IRQ: R419.2 U90.29(~{I2C1_IRQ})
PD_MS_I2C1_SCL: R393.1 R415.2 U90.27(I2C1_SCL)
PD_MS_I2C1_SDA: R394.1 R414.2 U90.28(I2C1_SDA)
PD_S_I2C2_IRQ: R169.2 U90.34(~{I2C2_IRQ})
PD_S_I2C2_SCL: R421.2 U90.32(I2C2_SCL)
PD_S_I2C2_SDA: R422.2 U90.33(I2C2_SDA)
PD_SPI_CLK: J11.7 R436.2 U34.6(CLK)
PD_SPI_MISO: J11.5 R146.2 R426.2 U34.2(DO(IO1))
PD_SPI_MOSI: J11.8 R431.2 U34.5(DI(IO0))
PD_SPI_SS: J11.9 R147.2 R439.2 U34.1(~{CS})
PD_VIN_3V3: C123.2 U90.5(VIN_3V3)
PP1_CABLE: C117.1 U90.25(PP1_CABLE)
PP2_CABLE: R447.2 U90.46(PP2_CABLE)
SoC_I2C0_SCL: R421.1 ; also on sheet 12 21 23 32 41
SoC_I2C0_SDA: R422.1 ; also on sheet 12 21 23 32 41
SoC_USB0_DRVVBUS: R416.1 R446.1 ; also on sheet 34
SPI_HOLDn: R145.2 U34.7(~{HOLD}(IO3))
SPI_WPn: R142.2 U34.3(~{WP}(IO2))
USB_TYPEC1_EARTH: C410.1 J13.SH1 J13.SH2 J13.SH3 J13.SH4 R157.1
USBC_CONN1_CC1: C113.1 D4.1(CATHODE) J13.A5(CC1) U90.24(C1_CC1)
USBC_CONN1_CC2: C116.1 D10.1(CATHODE) J13.B5(CC2) U90.26(C1_CC2)
USBC_CONN2_CC1: C131.1 U90.45(C2_CC1) ; also on sheet 35
USBC_CONN2_CC2: C130.1 U90.47(C2_CC2) ; also on sheet 35
VMAIN: C120.1 C128.1 C132.1 U90.1(PP_HV2) U90.11(PP_HV1) ; also on sheet 10 11 25
N17370891: R413.2 U90.17(GPIO1)
N17824845: R426.1 U90.36(SPI_MISO/GPIO8)
N17824852: R431.1 U90.37(SPI_MOSI/GPIO9)
N17824859: R436.1 U90.38(SPI_CLK/GPIO10)
N17824866: R439.1 U90.39(~{SPI_SS}/GPIO11)
N17827086: J11.1 R393.2 R395.2
N17827089: J11.3 R394.2 R396.2
N17849698: C445.1 Q10.1(S1) Q10.2(S2) Q10.5(S3) Q10.6(S4) Q10.8(S5) Q11.1(S1) Q11.2(S2) Q11.5(S3) Q11.6(S4) Q11.8(S5) R475.1
N17850096: C444.2 C445.2 C455.2 Q10.3(G) Q11.3(G) R467.1 R468.2 R475.2 R485.2
N17935978: Q9.3(G) R446.2 R449.2 R453.1
N17936309: Q9.1(D1) Q9.2(D2) Q9.5(D3) Q9.6(D4) Q9.8(D5) R467.2
N22682365: LD4.2(ANODE) R160.2

Not connected (* = marked no-connect by the designer): J11 4* 6*; J13 A2(TX1+)* A3(TX1-)* A6(D+_1)* A7(D-_1)* A8(SBU1)* A10(RX2-)* A11(RX2+)* B2(TX2+)* B3(TX2-)* B6(D+_2)* B7(D-_2)* B8(SBU2)* B10(RX1-)* B11(RX1+)*; U90 30(HPD1/GPIO3)* 31(HPD2/GPIO4)* 40(GPIO12)* 41(GPIO13)* 42(GPIO14/PWM)* 43(GPIO15/PWM)* 48(GPIO16/PP_EXT1)* 50(C1_USB_P/GPIO18)* 53(C1_USB_N/GPIO19)* 54(C2_USB_P/GPIO20)* 55(C2_USB_N/GPIO21)*

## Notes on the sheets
sheet 1
- AM62A STARTER KIT EVM
- TABLE OF CONTENTS
- PAGE
- CONTENTS
- PAGE
- CONTENTS
- REV
- E2
- 01
- TABLE OF CONTENTS
- 41
- OSCILLATOR
- VER
- 2.0
- 02
- REVISION HISTORY
- 42
- RESET
- 03
- BLOCK DIAGRAM AM62A SKEVM
- 43
- CAN FD WKUP SW
- 04
- BLOCK DIAGRAM XDS110
- 44
- ACCESSORIES
- 05
- POWER BLOCK DIAGRAM
- 06
- POWER SEQUENCE
- 07
- I2C TREE
- 08
- GPIO MAPPING TABLE
- 09
- USB TYPE-C POWER
- 10
- PERIPHERAL POWER SUPPLY-1
- 11
- PERIPHERAL POWER SUPPLY-2
- 12
- SOC POWER SUPPLY
- 13
- CURRENT MONITORING DEVICES
- 14
- SOC POWER
- 15
- SOC POWER CAPS AND VSS
- 16
- LPDDR4 INTERFACE
- 17
- M.2 CONNECTOR
- 18
- eMMC FLASH
- 19
- SD CARD INTERFACE
- 20
- OSPI INTERFACE
- 21
- BOARD ID EEPROM & TEMPERATURE SENSORS
- 22
- CPSW RGMII_1 ETHERNET PHY
- 23
- CPSW RGMII_2 ETHERNET CONNECTOR
- 24
- ETHERNET PHY CLOCK BUFFER & LED DRIVER
- 25
- TEST AUTOMATION
- 26
- BOOT MODE BUFFER & SWITCHES
- 27
- XDS110 DEBUGGER
- 28
- JTAG BUFFER
- 29
- JTAG 20 PIN cTI CONNECTOR
- 30
- FT4232 UART TO USB BRIDGE
- 31
- SOC WKUP & GPMC DOMAIN
- 32
- USER EXPANSION CONNECTOR
- 33
- MCU HEADER
- 34
- USB1 TYPE A
- 35
- USB0 TYPE-C DRP & TEST LEDs
- 36
- SoC UART1 FET SWITCH & BUFFER
- 37
- CSI INTERFACE
- 38
- AUDIO CODEC
- 39
- IO EXPANDER
- 40
- HDMI INTERFACE
sheet 2
- REVISION HISTORY
- VER #
- DATE
- DESCRIPTION OF CHANGES
- AUTHOR
- REVIEWED  BY
- APPROVED  BY
- 0.01
- 21 MARCH 2022
- Initial Draft
- Mistral Design Team
- 0.02
- 30 MARCH 2022
- Updated CSI , LPDDR4 & PD CONTROLLER SECTION
- Mistral Design Team
- 0.03
- 14 APR 2022
- Updated PMIC section
- Mistral Design Team
- 0.04
- 02 MAY 2022
- Updated Internal Review comments
- Mistral Design Team
- 0.05
- 04 MAY 2022
- Updated SoC Decaps & CSI FET connections for routing ease
- Mistral Design Team
- 0.06
- 09 MAY 2022
- Updated PMIC section
- Mistral Design Team
- 0.07
- 10 MAY 2022
- Net swapping in OSPI and HDMI groups of signals
- Mistral Design Team
- 0.08
- 11 MAY 2022
- Updated Power supply-2 (VCC_3V3_MAIN) section with new regulator, replaced RGMII2
  PHY section for accomodating ethernet ADD-ON boards(Industrial and Automotive PHY based)
- Mistral Design Team
- 0.09
- 12 MAY 2022
- Added Matting Connectors for ADD-ON boards and main board
  Updated power achitecture and I2C tree digrams
- Mistral Design Team
- 0.10
- 12 MAY 2022
- Added Matting Connectors for ADD-ON boards and main board
- Mistral Design Team
- E1
- 0.11
- 13 MAY 2022
- Added 3T caps for VDD_LPDDR4 SOC power rail
- Mistral Design Team
- 0.12
- 16 MAY 2022
- TI Review Comments implemented
- Mistral Design Team
- 0.13
- 18 MAY 2022
- Updated single port PD controller to Dual PD to match software requirements
- Mistral Design Team
- 0.14
- 19 MAY 2022
- Separated RGMII Add On Boards to individual schematics
- Mistral Design Team
- 0.15
- 24 MAY 2022
- Updated PMIC GPIO connections as per TI review comments
- Mistral Design Team
- 0.16
- 27 MAY 2022
- TI Review Comments implemented
- Mistral Design Team
- 0.17
- 30 MAY 2022
- Updated M.2 connector section
  Added I2C signals for RGMII Add-On connector
  Added LDO for VDD_CANUART signals
  Part References Back annotated from PCB file
- Mistral Design Team
- 0.18
- 31 MAY 2022
- Updated to SOC I2C0 for RGMII board detect
  Removed ground connection from M.2 screw
- Mistral Design Team
- 0.19
- 1 JUNE 2022
- Modified MCU User Interrupt signals
  Updated TI review comments
- Mistral Design Team
- 0.20
- 15 JUNE 2022
- CSI MIPI Connector (J1) marked as present as per TI Comments
- Mistral Design Team
- 1.0
- 17 JUNE 2022
- Baselined
- Mistral Design Team
- 1.01
- 19 SEPT 2022
- Updated design with changes mentioned in "AM62A_SKEVM_Change_List_For_REV_E2" document
- Mistral Design Team
- E2
- 1.02
- 20 SEPT 2022
- Replaced the INA filter resistors from existing 10E to 0E as per TI recommendations
- Mistral Design Team
- 2.0
- 20 SEPT 2022
- Baselined
- Mistral Design Team
sheet 3
- BLOCK DIAGRAM AM62A-SKEVM
sheet 4
- BLOCK DIAGRAM_XDS110
sheet 5
- POWER BLOCK DGM
sheet 6
- POWER SEQUENCE
sheet 7
- I2C TREE
sheet 8
- GPIO MAPPING TABLE
sheet 9
- USB TYPE-C POWER
- Silk: TYPE-C PWR
- TYPE-C DUAL PD CONTROLLER
- POWER INDICATION LED: VBUS_TYPEC1
- BP_NoWait
  Safe Configuration
- EXTERNAL POWER PATH FOR SOURCING, 5V/0.5A
- I2C Slave
   Address
- Port1
- Port2
- I2C2(Default)
- 0x38
- 0x3F
- I2C1
- 0x20
- 0x24
- SPI EEPROM & PROGRAMMING HEADER
